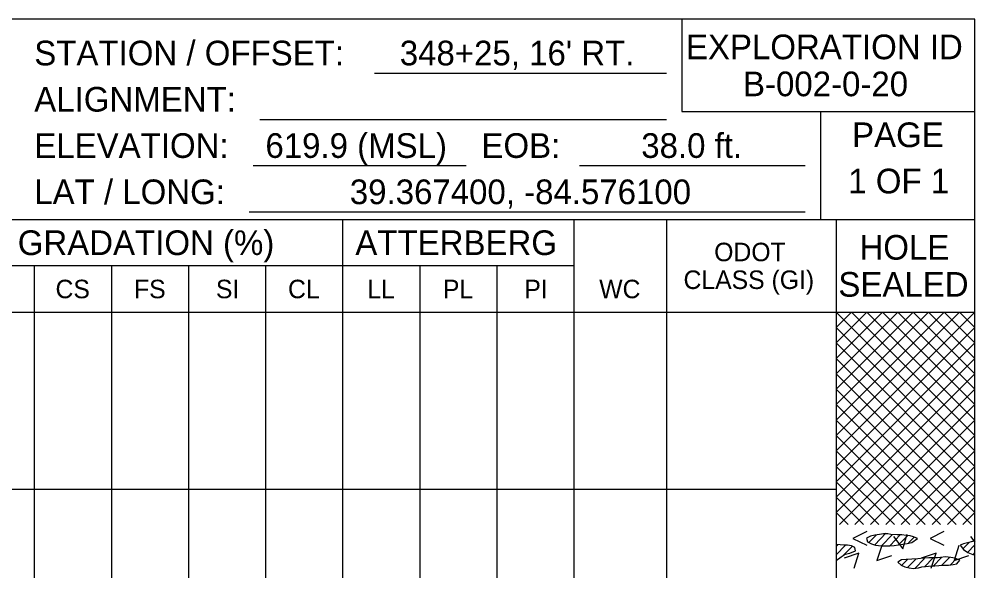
# Model space of a CAD drawing. Extents: x -0.01 to 0.83, y -0.63 to 1.27.
# Drawn here: x 0.5751 to 0.8333, y 1.1259 to 1.275 of the extents above; entities that cross this region are included whole.
import ezdxf

# ---------------------------------------------------------------- set-up
doc = ezdxf.new("R2010")
doc.units = 0

msp = doc.modelspace()

# ---------------------------------------------------------------- linework, layer by layer
for points in [[(0, 0), (0.83333, 0), (0.83333, 1.275), (0, 1.275)], [(0, 0), (0.83333, 0), (0.83333, 1.275), (0, 1.275)], [(0, 0), (0.83333, 0), (0.83333, 1.275), (0, 1.275)], [(0, 0), (0.83333, 0), (0.83333, 1.275), (0, 1.275)], [(0, 0), (0.83333, 0), (0.83333, 1.275), (0, 1.275)], [(0.81233, 1.13565), (0.81063, 1.13577), (0.80977, 1.13591), (0.8086, 1.13591), (0.80755, 1.13577), (0.80632, 1.13557), (0.80513, 1.13533), (0.80403, 1.1348), (0.80436, 1.13374), (0.80536, 1.13318), (0.80647, 1.13288), (0.8073, 1.13273), (0.80824, 1.13265), (0.80926, 1.13264), (0.81035, 1.13269), (0.81149, 1.1328), (0.81267, 1.13294), (0.81386, 1.13313), (0.81506, 1.13334), (0.81625, 1.13357), (0.81783, 1.13466), (0.81673, 1.13515), (0.81585, 1.13536), (0.8148, 1.13551), (0.81361, 1.13562)], [(0.83265, 1.13384), (0.83136, 1.13353), (0.83028, 1.13326), (0.82934, 1.13286), (0.83026, 1.13166), (0.83142, 1.1309), (0.83279, 1.13032), (0.83333, 1.13022), (0.83333, 1.13393)], [(0.79583, 1.12874), (0.79719, 1.12973), (0.79831, 1.13044), (0.79951, 1.13071), (0.80111, 1.13131), (0.80086, 1.13219), (0.80002, 1.13267), (0.79889, 1.13286), (0.79791, 1.13289), (0.79694, 1.13295), (0.79583, 1.13303)], [(0.82537, 1.12969), (0.82408, 1.12954), (0.82319, 1.12948), (0.82214, 1.12946), (0.82091, 1.12942), (0.81947, 1.12933), (0.81792, 1.12921), (0.81632, 1.12909), (0.81475, 1.12899), (0.81348, 1.12889), (0.81247, 1.12825), (0.81337, 1.12749), (0.81444, 1.12699), (0.81561, 1.1267), (0.81675, 1.12659), (0.81807, 1.12671), (0.81896, 1.12698), (0.82003, 1.12713), (0.82157, 1.12725), (0.82253, 1.12731), (0.82362, 1.12737), (0.82483, 1.12743), (0.82618, 1.12749), (0.82745, 1.1276), (0.82842, 1.12778), (0.82927, 1.12883), (0.82791, 1.12935), (0.82679, 1.12955)]]:
    msp.add_lwpolyline(points, close=True)
for points in [[(0.75417, 1.275), (0.75417, 1.25), (0.83333, 1.25)], [(0.67111, 1.26041), (0.75, 1.26041)], [(0.79167, 1.22083), (0.79167, 1.25)], [(0.64014, 1.24791), (0.75, 1.24791)], [(0.63833, 1.23541), (0.69583, 1.23541)], [(0.72653, 1.23541), (0.7875, 1.23541)], [(0.63722, 1.22291), (0.7875, 1.22291)], [(0, 1.22083), (0.83333, 1.22083)], [(0, 1.22083), (0.83333, 1.22083)], [(0, 1.22083), (0.83333, 1.22083)], [(0, 1.22083), (0.83333, 1.22083)], [(0, 1.22083), (0.83333, 1.22083)], [(0.6625, 1.22083), (0.6625, -0.62183)], [(0.725, 1.22083), (0.725, -0.62183)], [(0.75, 1.22083), (0.75, -0.62183)], [(0.75, 1.22083), (0.75, -0.62183)], [(0.79583, 1.22083), (0.79583, -0.62183)], [(0.725, 1.20833), (0.55833, 1.20833)], [(0.57917, 1.20833), (0.57917, -0.62183)], [(0.6, 1.20833), (0.6, -0.62183)], [(0.62083, 1.20833), (0.62083, -0.62183)], [(0.64167, 1.20833), (0.64167, -0.62183)], [(0.68333, 1.20833), (0.68333, -0.62183)], [(0.70417, 1.20833), (0.70417, -0.62183)], [(0.725, 1.20833), (0.725, -0.62183)], [(0, 1.19583), (0.83333, 1.19583)], [(0, 1.19583), (0.83333, 1.19583)], [(0, 1.19583), (0.83333, 1.19583)], [(0, 1.19583), (0.83333, 1.19583)], [(0, 1.19583), (0.83333, 1.19583)], [(0.79583, 1.19583), (0.83333, 1.15833)], [(0.79583, 1.19166), (0.8, 1.19583)], [(0.79583, 1.1875), (0.80417, 1.19583)], [(0.79583, 1.18333), (0.80833, 1.19583)], [(0.79583, 1.17916), (0.8125, 1.19583)], [(0.79583, 1.175), (0.81667, 1.19583)], [(0.79583, 1.17083), (0.82083, 1.19583)], [(0.79583, 1.16666), (0.825, 1.19583)], [(0.79583, 1.1625), (0.82917, 1.19583)], [(0.79583, 1.15833), (0.83333, 1.19583)], [(0.8, 1.19583), (0.83333, 1.1625)], [(0.80417, 1.19583), (0.83333, 1.16666)], [(0.80833, 1.19583), (0.83333, 1.17083)], [(0.8125, 1.19583), (0.83333, 1.175)], [(0.81667, 1.19583), (0.83333, 1.17916)], [(0.82083, 1.19583), (0.83333, 1.18333)], [(0.825, 1.19583), (0.83333, 1.1875)], [(0.82917, 1.19583), (0.83333, 1.19166)], [(0.83333, 1.19583), (0.83333, 1.19583)], [(0.83333, 1.13843), (0.83333, 1.19583)], [(0.79583, 1.19166), (0.83333, 1.15416)], [(0.79583, 1.15416), (0.83333, 1.19166)], [(0.79583, 1.1875), (0.83333, 1.15)], [(0.79583, 1.15), (0.83333, 1.1875)], [(0.79583, 1.18333), (0.83333, 1.14583)], [(0.79583, 1.14583), (0.83333, 1.18333)], [(0.79583, 1.17916), (0.83333, 1.14166)], [(0.79583, 1.14166), (0.83333, 1.17916)], [(0.79583, 1.175), (0.8324, 1.13843)], [(0.79677, 1.13843), (0.83333, 1.175)], [(0.79583, 1.17083), (0.82823, 1.13843)], [(0.80093, 1.13843), (0.83333, 1.17083)], [(0.79583, 1.16666), (0.82407, 1.13843)], [(0.8051, 1.13843), (0.83333, 1.16666)], [(0.79583, 1.1625), (0.8199, 1.13843)], [(0.80927, 1.13843), (0.83333, 1.1625)], [(0.79583, 1.15833), (0.81573, 1.13843)], [(0.81343, 1.13843), (0.83333, 1.15833)], [(0.79583, 1.15416), (0.81157, 1.13843)], [(0.8176, 1.13843), (0.83333, 1.15416)], [(0.79583, 1.15), (0.8074, 1.13843)], [(0.82177, 1.13843), (0.83333, 1.15)], [(0.55833, 1.148), (0.57917, 1.148)], [(0.57917, 1.148), (0.6, 1.148)], [(0.6, 1.148), (0.62083, 1.148)], [(0.62083, 1.148), (0.64167, 1.148)], [(0.64167, 1.148), (0.6625, 1.148)], [(0.6625, 1.148), (0.68333, 1.148)], [(0.68333, 1.148), (0.70417, 1.148)], [(0.70417, 1.148), (0.725, 1.148)], [(0.725, 1.148), (0.75, 1.148)], [(0.75, 1.148), (0.79583, 1.148)], [(0.79583, 1.14583), (0.80323, 1.13843)], [(0.82593, 1.13843), (0.83333, 1.14583)], [(0.79583, 1.14166), (0.79907, 1.13843)], [(0.8301, 1.13843), (0.83333, 1.14166)], [(0.80412, 1.13658), (0.80038, 1.1347), (0.80412, 1.13283)], [(0.82496, 1.13658), (0.82121, 1.1347), (0.82496, 1.13283)], [(0.83333, -0.62183), (0.83333, 1.13843)], [(0.80465, 1.13354), (0.80667, 1.13561)], [(0.80626, 1.13297), (0.80928, 1.13607)], [(0.80809, 1.13264), (0.81111, 1.13573)], [(0.81041, 1.1328), (0.81318, 1.13563)], [(0.81134, 1.13524), (0.81384, 1.13186), (0.81503, 1.13586)], [(0.81264, 1.13288), (0.81518, 1.13548)], [(0.81536, 1.13345), (0.81699, 1.13511)], [(0.83217, 1.13524), (0.83333, 1.13368)], [(0.7963, 1.13299), (0.79583, 1.13251)], [(0.79834, 1.13286), (0.79583, 1.13029)], [(0.79786, 1.13016), (0.80023, 1.13259)], [(0.80818, 1.13275), (0.80687, 1.12875), (0.81087, 1.13006)], [(0.82901, 1.13275), (0.8277, 1.12875), (0.8317, 1.13006)], [(0.8301, 1.13187), (0.83184, 1.13366)], [(0.83131, 1.1309), (0.83333, 1.13298)], [(0.80069, 1.12667), (0.802, 1.13067), (0.798, 1.12935)], [(0.81519, 1.12906), (0.81354, 1.12736)], [(0.81514, 1.1268), (0.81748, 1.12919)], [(0.81709, 1.12658), (0.81974, 1.1293)], [(0.82152, 1.12667), (0.82284, 1.13067), (0.81884, 1.12935)], [(0.8197, 1.12703), (0.82203, 1.12943)], [(0.82202, 1.1272), (0.8243, 1.12954)], [(0.82431, 1.12733), (0.82644, 1.12952)], [(0.82663, 1.1275), (0.82834, 1.12925)], [(0.83285, 1.13027), (0.83333, 1.13076)]]:
    msp.add_lwpolyline(points)

# ---------------------------------------------------------------- texts
for s, height, p in [('EXPLORATION ID', 0.0066667, (0.75526, 1.26416)), ('STATION / OFFSET:', 0.0066667, (0.57917, 1.2625)), ("348+25, 16' RT.", 0.0066667, (0.67793, 1.2625)), ('B-002-0-20', 0.006667, (0.77068, 1.25416)), ('ALIGNMENT:', 0.006667, (0.57917, 1.25)), ('PAGE', 0.006667, (0.80015, 1.24041)), ('ELEVATION:', 0.006667, (0.57917, 1.2375)), ('619.9 (MSL)', 0.0066667, (0.64163, 1.2375)), ('EOB:', 0.006667, (0.7, 1.2375)), ('38.0 ft.', 0.006667, (0.74319, 1.2375)), ('1 OF 1', 0.006667, (0.79912, 1.22791)), ('LAT / LONG:', 0.0066667, (0.57917, 1.225)), ('39.367400, -84.576100', 0.0066667, (0.66444, 1.225)), ('GRADATION (%)', 0.0066667, (0.5747, 1.21125)), ('ATTERBERG', 0.006667, (0.66592, 1.21125)), ('HOLE', 0.006667, (0.80215, 1.21)), ('ODOT', 0.005, (0.76289, 1.20958)), ('CLASS (GI)', 0.005, (0.7546, 1.20208)), ('SEALED', 0.006667, (0.79645, 1.2)), ('CS', 0.005, (0.58491, 1.19958)), ('FS', 0.005, (0.60613, 1.19958)), ('SI', 0.005, (0.62826, 1.19958)), ('CL', 0.005, (0.64774, 1.19958)), ('LL', 0.005, (0.66916, 1.19958)), ('PL', 0.005, (0.6896, 1.19958)), ('PI', 0.005, (0.71159, 1.19958)), ('WC', 0.005, (0.73182, 1.19958))]:
    msp.add_text(s, height=height).set_placement(p)

doc.saveas('drawing.dxf')
